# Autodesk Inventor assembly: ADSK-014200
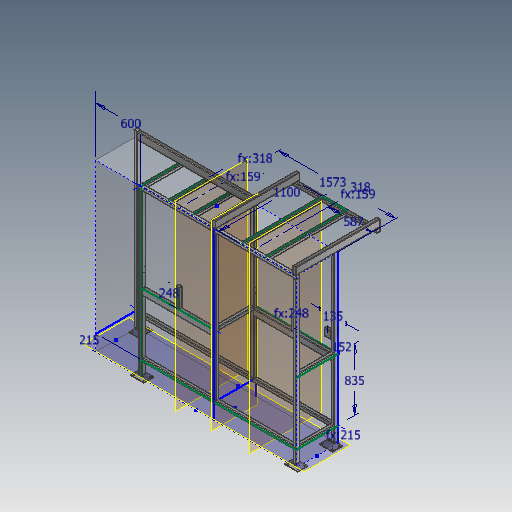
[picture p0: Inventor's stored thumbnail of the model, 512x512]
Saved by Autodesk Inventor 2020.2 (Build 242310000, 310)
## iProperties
_SolveAssemblyDoc: Frame Generator Solve Assembly
_Version: 15.0.0
Created: 2019-10
Part Number: ADSK-014200
Document SubType Name: Assembly
Designer: lutzd
Mass: 2.64796e+07 g
Surface Area: 299637 cm^2
Volume: 3.37795e+06 cm^3
Density: 7.83897 g/cm^3
VLDS_Profile: Default Assembly
VLDS_TimeStamp: 2016-07-29
VLDS_FailCnt: 0
VLDS_AcceptCnt: 0
Dimensions: 1166,7x2325x2753,9 mm
Mass: 26479,644 kg
DocNumber: ADSK-014200
Folder: .
VDS_Category: 3D Komponenten
VDS_NumSchm: Autodesk
Title: Frame
Author: lutzd
Revision Number: -
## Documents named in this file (5)
- D:\07 - DEMODATEN\OTX 2019 - Dataset - UPDATE - Dez2019\Designs\07-Packing machine\ADSK-014200.iam
- D:\07 - DEMODATEN\OTX 2019 - Dataset - UPDATE - Dez2019\Designs\07-Packing machine\Parts\ADSK-014199.ipt
- D:\07 - DEMODATEN\OTX 2019 - Dataset - UPDATE - Dez2019\Designs\07-Packing machine\ADSK-014200\Frame\ADSK-014201.iam
- D:\07 - DEMODATEN\OTX 2019 - Dataset - UPDATE - Dez2019\Designs\07-Packing machine\Parts\ADSK-011287.ipt
- D:\07 - DEMODATEN\OTX 2019 - Dataset - UPDATE - Dez2019\Designs\07-Packing machine\Parts\ADSK-011288.ipt
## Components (10 placed, 4 different names)
1. ADSK-014199:1 — Fluchtend:2, Fluchtend:3, Fluchtend:5, Fluchtend:6
2. ADSK-014201:1 [sub-assembly] — Passend:10, Passend:11, Passend:12, Fluchtend:1, Passend:16, Passend:17, Passend:18, Fluchtend:7
3. ADSK-011287:1 — Fluchtend:5, Fluchtend:7
4. ADSK-011288:1 — Passend:18
5. ADSK-011287:2 — Fluchtend:1, Fluchtend:3
6. ADSK-011288:2 — Passend:11
7. ADSK-011287:3 — Passend:12, Fluchtend:2
8. ADSK-011288:3 — Passend:10
9. ADSK-011287:4 — Passend:17, Fluchtend:6
10. ADSK-011288:4 — Passend:16
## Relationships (12: Mate 6, Flush 6)
- Passend:10 [Mate]: ADSK-014201:1 ↔ ADSK-011288:3
- Passend:11 [Mate]: ADSK-014201:1 ↔ ADSK-011288:2
- Passend:12 [Mate]: ADSK-014201:1 ↔ ADSK-011287:3
- Fluchtend:1 [Flush]: ADSK-014201:1 ↔ ADSK-011287:2
- Fluchtend:2 [Flush]: ADSK-014199:1 ↔ ADSK-011287:3
- Fluchtend:3 [Flush]: ADSK-014199:1 ↔ ADSK-011287:2
- Passend:16 [Mate]: ADSK-014201:1 ↔ ADSK-011288:4
- Passend:17 [Mate]: ADSK-014201:1 ↔ ADSK-011287:4
- Passend:18 [Mate]: ADSK-014201:1 ↔ ADSK-011288:1
- Fluchtend:5 [Flush]: ADSK-014199:1 ↔ ADSK-011287:1
- Fluchtend:6 [Flush]: ADSK-014199:1 ↔ ADSK-011287:4
- Fluchtend:7 [Flush]: ADSK-014201:1 ↔ ADSK-011287:1
## Named parameters: d55_d50 = 45 mm, d56_d47 = 0, d57_d49 = 0, d3_d55_d50 = 45 mm, d4_d56_d47 = 0, d5_d57_d49 = 0, d51_d44 = 0, d52_d45 = 0, d53_d46 = 0, d15_d51_d44 = 0, d16_d52_d45 = 0, d17_d53_d46 = 0
